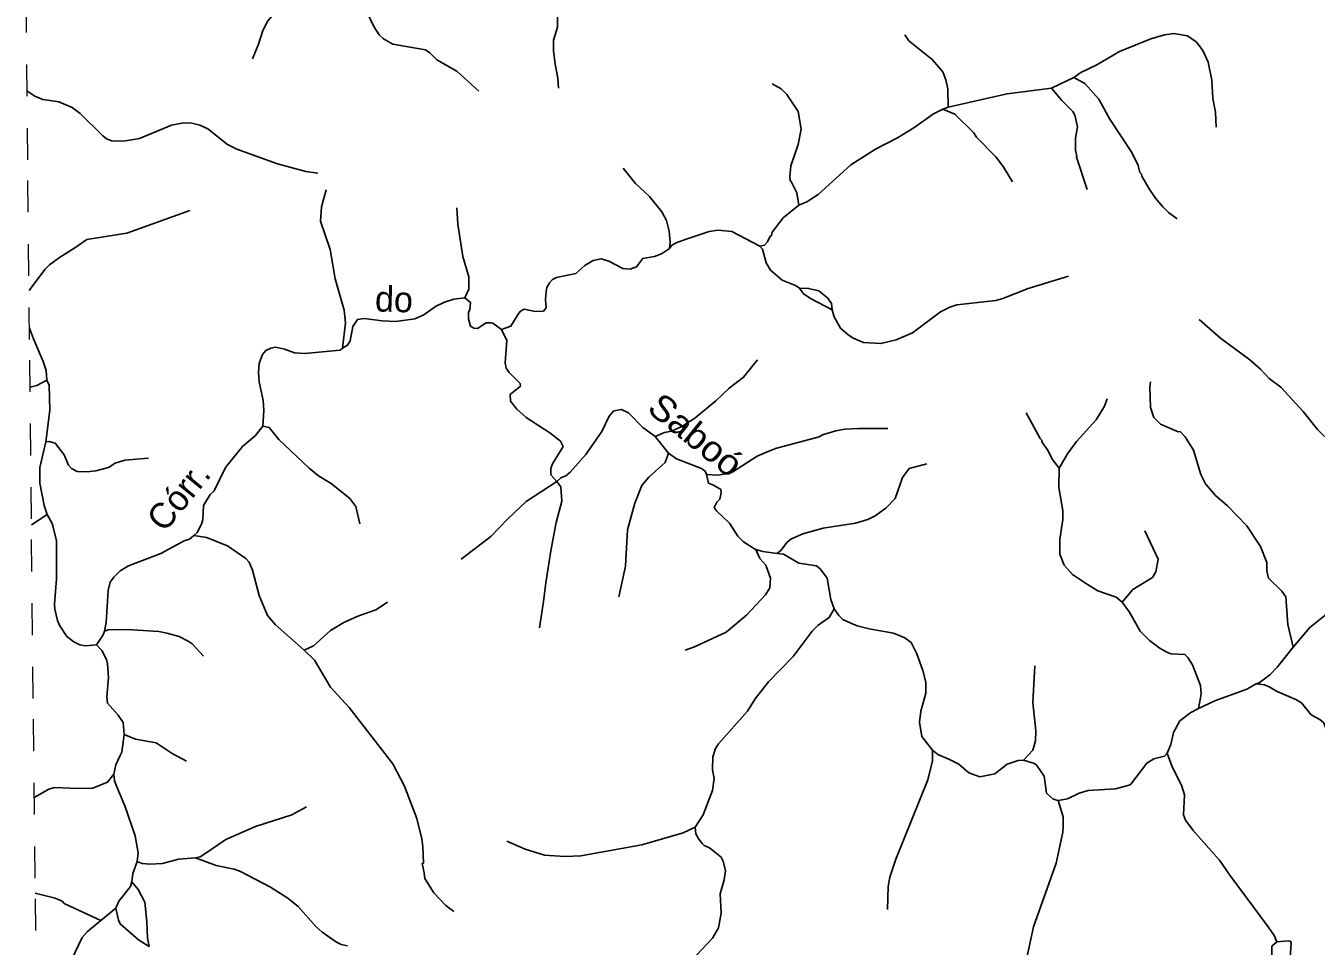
# Model space of a CAD drawing. Extents: x 346.5 to 372.4, y 7400.3 to 7428.2.
# Drawn here: x 346.625 to 350.684, y 7417.62 to 7420.515 of the extents above; entities that cross this region are included whole.
import ezdxf
from ezdxf.enums import TextEntityAlignment as Align

# ---------------------------------------------------------------- set-up
doc = ezdxf.new("R2010")
doc.units = 0
doc.header["$LTSCALE"] = 0.032
doc.linetypes.add('SHORT_DASHED', pattern=[2.7, 1.5, -1.2])
for name, color, linetype, lineweight in [('2', 7, 'Continuous', 25), ('53', 7, 'SHORT_DASHED', 13), ('7', 7, 'Continuous', 25)]:
    doc.layers.add(name, color=color, linetype=linetype, lineweight=lineweight)
doc.layers.add('61', color=7, linetype='Continuous')

msp = doc.modelspace()

# ---------------------------------------------------------------- linework, layer by layer
at = {"layer": '2'}
for points in [[(349.0587, 7419.6897), (349.0876, 7419.689), (349.1197, 7419.681), (349.1486, 7419.6579), (349.1598, 7419.6417), (349.1615, 7419.6212), (349.0936, 7419.6576), (349.071, 7419.6725)], [(346.9092, 7417.7395), (346.9181, 7417.7609), (346.9546, 7417.8075), (346.9588, 7417.8226), (346.9792, 7417.7976), (347.0001, 7417.758), (347.0065, 7417.6967), (347.0078, 7417.645), (347.0131, 7417.6189), (346.9804, 7417.6401), (346.9224, 7417.69), (346.9169, 7417.7019)], [(350.5445, 7417.5746), (350.5445, 7417.6194), (350.5603, 7417.6339), (350.5969, 7417.6371), (350.6034, 7417.6351), (350.6057, 7417.6305), (350.6019, 7417.5687), (350.6142, 7417.5248), (350.6164, 7417.4995), (350.6076, 7417.4794), (350.5878, 7417.4716), (350.5648, 7417.4992), (350.5572, 7417.5453)]]:
    msp.add_lwpolyline(points, close=True, dxfattribs=at)
at = {"layer": '53'}
msp.add_lwpolyline([(346.7311, 7410.4893), (346.7252, 7411.0543), (346.7194, 7411.6193), (346.7135, 7412.1842), (346.7076, 7412.7492), (346.7018, 7413.3141), (346.6959, 7413.8791), (346.69, 7414.444), (346.6841, 7415.009), (346.6783, 7415.574), (346.6724, 7416.1389), (346.6665, 7416.7039), (346.6607, 7417.2688), (346.6548, 7417.8338), (346.649, 7418.3987), (346.6431, 7418.9637), (346.6372, 7419.5286), (346.6314, 7420.0936), (346.6255, 7420.6585)], dxfattribs=at)
at = {"layer": '7'}
for p, q in [((346.6922, 7418.9778), (346.6433, 7418.9453)), ((346.9092, 7417.7395), (346.8612, 7417.7011))]:
    msp.add_line(p, q, dxfattribs=at)
for points in [[(348.1783, 7421.1943), (348.1763, 7421.1774), (348.1508, 7421.0993), (348.1413, 7421.0547), (348.1341, 7420.9622), (348.1349, 7420.9335), (348.1436, 7420.9048), (348.1532, 7420.8857), (348.217, 7420.7885), (348.2361, 7420.7534), (348.2839, 7420.6307), (348.2935, 7420.5972), (348.2983, 7420.5398), (348.2975, 7420.5111), (348.2855, 7420.4697), (348.2855, 7420.4378), (348.2903, 7420.3948), (348.299, 7420.3502), (348.3015, 7420.3191)], [(347.5673, 7420.8051), (347.518, 7420.7311), (347.4981, 7420.6849), (347.4806, 7420.6315), (347.4487, 7420.5908), (347.4073, 7420.555), (347.3873, 7420.5311), (347.3714, 7420.5), (347.3578, 7420.457), (347.3387, 7420.4115)], [(347.5673, 7420.8051), (347.5834, 7420.7685), (347.6232, 7420.7399), (347.6479, 7420.704), (347.6902, 7420.5765), (347.7205, 7420.5127), (347.7372, 7420.4872), (347.7507, 7420.4737), (347.7802, 7420.4569), (347.8823, 7420.4394), (347.8966, 7420.4298), (347.9181, 7420.4083), (347.9811, 7420.3725), (348.0504, 7420.3095)], [(349.3909, 7420.4864), (349.4036, 7420.4681), (349.4769, 7420.4091), (349.5096, 7420.3701), (349.5192, 7420.3454), (349.5255, 7420.3167), (349.5273, 7420.2596)], [(350.3703, 7420.1963), (350.3679, 7420.2434), (350.3592, 7420.2864), (350.356, 7420.3438), (350.3448, 7420.4012), (350.3289, 7420.4354), (350.3193, 7420.449), (350.3066, 7420.4649), (350.2795, 7420.484), (350.2364, 7420.4904), (350.2077, 7420.4872), (350.1647, 7420.4745), (350.0659, 7420.4338), (349.995, 7420.3924), (349.9439, 7420.3677), (349.9226, 7420.3521), (349.8517, 7420.319)], [(349.9226, 7420.3521), (349.9567, 7420.3334), (350.0005, 7420.284), (350.0356, 7420.2211), (350.1041, 7420.1167), (350.1249, 7420.0752), (350.1296, 7420.0537), (350.1352, 7420.0489), (350.136, 7420.0425), (350.1591, 7420.0019), (350.179, 7419.9724), (350.2022, 7419.9453), (350.2197, 7419.9278), (350.2468, 7419.9079)], [(347.5436, 7420.0513), (347.5061, 7420.0569), (347.4168, 7420.0808), (347.2893, 7420.127), (347.2598, 7420.1421), (347.1985, 7420.1908), (347.173, 7420.2027), (347.1475, 7420.2091), (347.122, 7420.2099), (347.0837, 7420.2027), (346.9833, 7420.1605), (346.9323, 7420.1517), (346.8956, 7420.1533), (346.8797, 7420.1597), (346.8677, 7420.1692), (346.7968, 7420.2394), (346.7713, 7420.2585), (346.7291, 7420.276), (346.6789, 7420.2832), (346.6534, 7420.2936), (346.6292, 7420.3103)], [(348.9733, 7420.3326), (349.0012, 7420.3167), (349.0195, 7420.2992), (349.0546, 7420.2458), (349.0641, 7420.19), (349.0546, 7420.1414), (349.0322, 7420.0744), (349.0283, 7420.0409), (349.0298, 7420.0274), (349.033, 7420.0258), (349.0506, 7419.9899), (349.057, 7419.9512)], [(349.8517, 7420.319), (349.712, 7420.3007), (349.5273, 7420.2596), (349.5104, 7420.2529)], [(349.8517, 7420.319), (349.8842, 7420.28), (349.9192, 7420.2458), (349.9256, 7420.2338), (349.9336, 7420.1971), (349.9272, 7420.1621), (349.9272, 7420.1238), (349.932, 7420.1055), (349.9304, 7420.1015), (349.9639, 7420.0003)], [(349.5104, 7420.2529), (349.4809, 7420.2378), (349.4188, 7420.1939), (349.367, 7420.1629), (349.2984, 7420.127), (349.2211, 7420.0776), (349.1175, 7419.9843), (349.0825, 7419.9612), (349.057, 7419.9512)], [(349.5104, 7420.2529), (349.5479, 7420.237), (349.6068, 7420.1796), (349.6164, 7420.1653), (349.677, 7420.1031), (349.7001, 7420.072), (349.7288, 7420.0242)], [(348.5047, 7420.0672), (348.5437, 7420.0186), (348.5875, 7419.978), (348.6266, 7419.9294), (348.6409, 7419.9023), (348.6489, 7419.8688), (348.6523, 7419.8345), (348.6501, 7419.8149)], [(347.5699, 7419.9987), (347.5555, 7419.9453), (347.5523, 7419.9007), (347.5834, 7419.8114), (347.5985, 7419.719), (347.6272, 7419.6202), (347.6312, 7419.5803), (347.6213, 7419.5012)], [(346.6356, 7419.6827), (346.6852, 7419.7485), (346.6996, 7419.7628), (346.7315, 7419.7859), (346.7801, 7419.817), (346.8175, 7419.8425), (346.9435, 7419.8632), (347.1419, 7419.9342)], [(347.9811, 7419.9429), (347.9843, 7419.8911), (348.0002, 7419.7891), (348.0193, 7419.7254), (348.0193, 7419.6871), (348.0068, 7419.6595)], [(349.057, 7419.9512), (349.0075, 7419.911), (348.9733, 7419.8664), (348.9709, 7419.8552), (348.9669, 7419.8529), (348.9585, 7419.8356), (348.9489, 7419.8253), (348.9348, 7419.8219)], [(348.9348, 7419.8219), (348.8466, 7419.868), (348.8035, 7419.872), (348.7748, 7419.868), (348.7031, 7419.8441), (348.6715, 7419.8321), (348.657, 7419.8239), (348.6501, 7419.8149)], [(348.6501, 7419.8149), (348.625, 7419.7979), (348.6027, 7419.7899), (348.566, 7419.7827), (348.5469, 7419.7572), (348.5262, 7419.7492), (348.5039, 7419.7516), (348.4592, 7419.7747), (348.4353, 7419.7819), (348.4098, 7419.7771), (348.3843, 7419.7612), (348.3556, 7419.7357), (348.2951, 7419.723), (348.2823, 7419.7174), (348.2727, 7419.707), (348.2648, 7419.6919), (348.2624, 7419.6791), (348.26, 7419.6536), (348.2624, 7419.6281), (348.2536, 7419.6178), (348.2281, 7419.6162), (348.1931, 7419.6233), (348.1819, 7419.6177), (348.1739, 7419.6082), (348.1516, 7419.5699), (348.1221, 7419.5598)], [(348.9348, 7419.8219), (348.943, 7419.8122), (348.9541, 7419.7692), (348.9677, 7419.7469), (349.0051, 7419.715), (349.0463, 7419.6985), (349.0587, 7419.6897)], [(349.9057, 7419.727), (349.779, 7419.6887), (349.6993, 7419.6568), (349.677, 7419.6512), (349.5543, 7419.6369), (349.5319, 7419.6305), (349.5024, 7419.6154), (349.4148, 7419.5492), (349.363, 7419.5277), (349.3152, 7419.5157), (349.261, 7419.5189), (349.2283, 7419.5325), (349.2108, 7419.5436), (349.1884, 7419.5636), (349.1685, 7419.5994), (349.1615, 7419.6212)], [(348.0068, 7419.6595), (347.9715, 7419.6552), (347.9428, 7419.6456), (347.9141, 7419.6321), (347.8775, 7419.6058), (347.8488, 7419.593), (347.7898, 7419.5851), (347.7468, 7419.5867), (347.6894, 7419.5946), (347.6687, 7419.5915), (347.6543, 7419.5692), (347.6463, 7419.5237), (347.6371, 7419.5109), (347.6213, 7419.5012)], [(348.0068, 7419.6595), (348.0241, 7419.6449), (348.0225, 7419.6225), (348.0177, 7419.613), (348.0177, 7419.5931), (348.0241, 7419.5707), (348.0345, 7419.5636), (348.0464, 7419.5628), (348.0735, 7419.5811), (348.0895, 7419.5803), (348.095, 7419.5795), (348.1221, 7419.5598)], [(350.3169, 7419.5907), (350.3831, 7419.5325), (350.4755, 7419.4647), (350.5098, 7419.4353), (350.5369, 7419.4058), (350.5735, 7419.3779), (350.6437, 7419.3022), (350.6883, 7419.2448), (350.7313, 7419.2033), (350.764, 7419.1786), (350.7975, 7419.1595), (350.8612, 7419.142), (350.8772, 7419.1332), (350.8962, 7419.1144)], [(346.692, 7419.4007), (346.6892, 7419.4305), (346.6804, 7419.4592), (346.6494, 7419.5309), (346.6368, 7419.5644)], [(348.1221, 7419.5598), (348.1389, 7419.5253), (348.1333, 7419.4544), (348.1365, 7419.4385), (348.146, 7419.4249), (348.1803, 7419.3898), (348.1819, 7419.3819), (348.1492, 7419.3555), (348.15, 7419.3341), (348.1699, 7419.3094), (348.1994, 7419.283), (348.2736, 7419.2352), (348.3078, 7419.2081), (348.3158, 7419.1914), (348.2823, 7419.1372), (348.2775, 7419.1229), (348.2775, 7419.1021), (348.2964, 7419.0811)], [(347.6213, 7419.5012), (347.6144, 7419.4944), (347.5029, 7419.4847), (347.471, 7419.4863), (347.4392, 7419.4982), (347.4105, 7419.5038), (347.3961, 7419.5014), (347.3802, 7419.4942), (347.3698, 7419.4815), (347.3594, 7419.4528), (347.3571, 7419.4241), (347.3594, 7419.3954), (347.3722, 7419.3364), (347.3738, 7419.3046), (347.3712, 7419.2552)], [(348.9271, 7419.4648), (348.8832, 7419.4097), (348.8378, 7419.3755), (348.7963, 7419.3356), (348.7302, 7419.2806), (348.6892, 7419.2542), (348.6569, 7419.2397), (348.6349, 7419.2356), (348.605, 7419.2235)], [(346.692, 7419.4007), (346.6605, 7419.3835), (346.6388, 7419.3787)], [(346.6889, 7419.2064), (346.7012, 7419.3062), (346.6989, 7419.3848), (346.692, 7419.4007)], [(350.1631, 7419.3946), (350.1607, 7419.3779), (350.1631, 7419.3141), (350.1743, 7419.283), (350.195, 7419.2615), (350.25, 7419.2376), (350.2564, 7419.2384), (350.2723, 7419.2217), (350.2986, 7419.1802), (350.3217, 7419.1037), (350.3368, 7419.0742), (350.3679, 7419.0376), (350.4054, 7419.0049), (350.4667, 7418.942), (350.5098, 7418.8774), (350.5297, 7418.8264), (350.5297, 7418.8009), (350.5345, 7418.7778), (350.5767, 7418.7363), (350.5887, 7418.7188), (350.595, 7418.6319), (350.6125, 7418.5604)], [(350.0268, 7419.342), (350.0189, 7419.3189), (349.9926, 7419.2751), (349.9304, 7419.2073), (349.9017, 7419.1691), (349.8764, 7419.1239)], [(348.2964, 7419.0811), (348.3086, 7419.093), (348.3238, 7419.0997), (348.3381, 7419.1109), (348.3867, 7419.1667), (348.4377, 7419.2392), (348.4608, 7419.287), (348.4752, 7419.3038), (348.4991, 7419.3077), (348.5214, 7419.2974), (348.5668, 7419.2512), (348.605, 7419.2235), (348.6472, 7419.1708)], [(349.7718, 7419.2974), (349.8164, 7419.2169), (349.822, 7419.2113), (349.822, 7419.2065), (349.8419, 7419.1779), (349.8539, 7419.1516), (349.8764, 7419.1239)], [(347.3712, 7419.2552), (347.3467, 7419.2249), (347.3068, 7419.1914), (347.2535, 7419.126), (347.2184, 7419.0519), (347.2056, 7419.0408), (347.1841, 7419.0057), (347.1825, 7418.9619), (347.1785, 7418.9475), (347.165, 7418.921), (347.154, 7418.9114)], [(347.3712, 7419.2552), (347.3905, 7419.2512), (347.4216, 7419.2137), (347.5164, 7419.1237), (347.5459, 7419.099), (347.5858, 7419.0758), (347.6448, 7419.028), (347.6639, 7419.0025), (347.6766, 7418.9483)], [(349.3367, 7419.2488), (349.245, 7419.2488), (349.202, 7419.2464), (349.1733, 7419.2408), (349.1318, 7419.2289), (349.1207, 7419.2217), (348.9836, 7419.185), (348.9549, 7419.1739), (348.9263, 7419.1611), (348.8498, 7419.1125), (348.8338, 7419.1069), (348.8019, 7419.1013), (348.767, 7419.1039)], [(346.6922, 7418.9778), (346.6828, 7419.0065), (346.6693, 7419.0766), (346.6693, 7419.1261), (346.6889, 7419.2064)], [(347.0112, 7419.1547), (346.9371, 7419.1491), (346.9068, 7419.1388), (346.8861, 7419.1252), (346.8462, 7419.1149), (346.8175, 7419.1117), (346.7873, 7419.1133), (346.7689, 7419.1221), (346.7601, 7419.1332), (346.7458, 7419.1659), (346.7179, 7419.2017), (346.6976, 7419.2072), (346.6889, 7419.2064)], [(348.6472, 7419.1708), (348.6362, 7419.1412), (348.5852, 7419.095), (348.5628, 7419.0687), (348.5413, 7419.0129), (348.5182, 7418.93), (348.5118, 7418.8152), (348.4911, 7418.7188)], [(348.6472, 7419.1708), (348.6728, 7419.1531), (348.7509, 7419.122), (348.7622, 7419.1142), (348.767, 7419.1039)], [(348.9893, 7418.8556), (349.0017, 7418.8659), (349.0195, 7418.8902), (349.0315, 7418.8997), (349.0697, 7418.9172), (349.1335, 7418.9348), (349.2355, 7418.9507), (349.2737, 7418.9619), (349.2976, 7418.9738), (349.3303, 7418.9977), (349.3598, 7419.028), (349.3829, 7419.0942), (349.4044, 7419.1221), (349.4594, 7419.1372)], [(349.8764, 7419.1239), (349.8746, 7419.0623), (349.8874, 7418.9906), (349.8874, 7418.9619), (349.8786, 7418.8997), (349.8778, 7418.8535), (349.8921, 7418.8184), (349.9184, 7418.7889), (349.9647, 7418.7578), (349.9981, 7418.7379), (350.0555, 7418.7172), (350.0745, 7418.7024)], [(347.9954, 7418.8368), (348.0879, 7418.9085), (348.1405, 7418.9635), (348.1994, 7419.0185), (348.2964, 7419.0811)], [(348.2964, 7419.0811), (348.3081, 7419.0646), (348.3118, 7419.0193), (348.2943, 7418.9523), (348.2767, 7418.8631), (348.2616, 7418.7626), (348.2536, 7418.7037), (348.2409, 7418.6216)], [(348.767, 7419.1039), (348.7725, 7419.0763), (348.7892, 7419.0702), (348.8115, 7419.0567), (348.8131, 7419.0464), (348.8083, 7419.0264), (348.7987, 7419.0161), (348.7908, 7419.0001), (348.7979, 7418.9898), (348.8394, 7418.9507), (348.8657, 7418.9093), (348.8832, 7418.8917), (348.9173, 7418.8701), (348.9214, 7418.8673)], [(346.8483, 7418.5682), (346.8128, 7418.565), (346.7952, 7418.5682), (346.7769, 7418.5769), (346.7546, 7418.5945), (346.733, 7418.6272), (346.7251, 7418.6447), (346.7163, 7418.6798), (346.7155, 7418.6957), (346.7219, 7418.7754), (346.7219, 7418.8949), (346.7107, 7418.942), (346.7084, 7418.9494), (346.6922, 7418.9778)], [(350.1456, 7418.926), (350.1878, 7418.8368), (350.1806, 7418.7969), (350.1695, 7418.7794), (350.1081, 7418.7419), (350.0745, 7418.7024)], [(350.897, 7418.9228), (350.8692, 7418.8949), (350.8469, 7418.8614), (350.8102, 7418.8312), (350.7911, 7418.8089), (350.7672, 7418.7642), (350.7544, 7418.7085), (350.7457, 7418.6957), (350.717, 7418.6638), (350.6644, 7418.6224), (350.6125, 7418.5604)], [(347.154, 7418.9114), (347.1403, 7418.9004), (347.1236, 7418.8949), (347.0502, 7418.8551), (346.9482, 7418.8168), (346.9219, 7418.8001), (346.9028, 7418.781), (346.8908, 7418.765), (346.8845, 7418.7387), (346.8781, 7418.6383), (346.8729, 7418.6105)], [(347.154, 7418.9114), (347.1937, 7418.9053), (347.2598, 7418.879), (347.318, 7418.8391), (347.3276, 7418.828), (347.3387, 7418.8025), (347.3594, 7418.7228), (347.3857, 7418.6598), (347.4112, 7418.6303), (347.5009, 7418.5511)], [(348.9214, 7418.8673), (348.9349, 7418.8396), (348.9533, 7418.8184), (348.9685, 7418.7778), (348.9661, 7418.7475), (348.9525, 7418.7252), (348.892, 7418.6614), (348.8282, 7418.608), (348.7286, 7418.561), (348.6991, 7418.5507)], [(348.9214, 7418.8673), (348.9435, 7418.8611), (348.9893, 7418.8556)], [(348.9893, 7418.8556), (349.0089, 7418.853), (349.057, 7418.8248), (349.1127, 7418.816), (349.1255, 7418.8057), (349.1462, 7418.7778), (349.1582, 7418.71), (349.1683, 7418.6807)], [(347.7635, 7418.7021), (347.7261, 7418.6782), (347.6703, 7418.6582), (347.6256, 7418.6383), (347.5842, 7418.6128), (347.5308, 7418.5642), (347.5009, 7418.5511)], [(349.1683, 7418.6807), (349.1526, 7418.6534), (349.1175, 7418.6295), (349.0992, 7418.6112), (349.0394, 7418.5307), (348.9621, 7418.451), (348.9199, 7418.3976), (348.8952, 7418.3594), (348.8043, 7418.2566), (348.7955, 7418.2414), (348.7868, 7418.2159), (348.786, 7418.1745), (348.7908, 7418.1474), (348.786, 7418.1092), (348.7557, 7418.0326), (348.7308, 7417.9941)], [(349.4773, 7418.2367), (349.4514, 7418.2701), (349.4443, 7418.2797), (349.4371, 7418.3243), (349.4411, 7418.3594), (349.457, 7418.416), (349.457, 7418.4502), (349.4474, 7418.4869), (349.4283, 7418.5395), (349.4108, 7418.5753), (349.3901, 7418.5897), (349.355, 7418.604), (349.2785, 7418.6184), (349.2403, 7418.6279), (349.2211, 7418.6359), (349.1956, 7418.6479), (349.1829, 7418.66), (349.1683, 7418.6807)], [(350.0745, 7418.7024), (350.0977, 7418.6702), (350.1304, 7418.6104), (350.1599, 7418.5817), (350.1942, 7418.5562), (350.2173, 7418.5435), (350.2285, 7418.5395), (350.2715, 7418.5371), (350.2803, 7418.5283), (350.2954, 7418.5044), (350.3209, 7418.4399), (350.3225, 7418.4136), (350.3201, 7418.4008), (350.3146, 7418.3678)], [(346.8729, 7418.6105), (346.8688, 7418.5994), (346.8483, 7418.5682)], [(346.8729, 7418.6105), (346.8848, 7418.615), (346.9451, 7418.616), (347.0439, 7418.6096), (347.0694, 7418.6048), (347.1076, 7418.5937), (347.1363, 7418.5793), (347.1491, 7418.5706), (347.1849, 7418.5323)], [(346.8483, 7418.5682), (346.8645, 7418.5499), (346.8797, 7418.522), (346.8829, 7418.5076), (346.8853, 7418.4646), (346.8805, 7418.404), (346.8821, 7418.3841), (346.9163, 7418.3466), (346.9315, 7418.3235), (346.9347, 7418.2855)], [(350.6125, 7418.5604), (350.5624, 7418.4981), (350.5385, 7418.4733), (350.5054, 7418.448), (350.4957, 7418.4446)], [(347.5009, 7418.5511), (347.5332, 7418.5196), (347.5842, 7418.4343), (347.6424, 7418.3705), (347.7802, 7418.1936), (347.8169, 7418.1235), (347.8551, 7418.0215), (347.8711, 7417.9577), (347.8743, 7417.9322), (347.8767, 7417.8812), (347.8727, 7417.8804), (347.8783, 7417.8509), (347.8807, 7417.8326), (347.9085, 7417.7872), (347.9468, 7417.7481), (347.9723, 7417.729)], [(349.7997, 7418.502), (349.7933, 7418.3865), (349.8021, 7418.2972), (349.8013, 7418.2654), (349.7933, 7418.2367), (349.7635, 7418.2045)], [(350.4957, 7418.4446), (350.466, 7418.4287), (350.3655, 7418.3913), (350.3146, 7418.3678)], [(350.4957, 7418.4446), (350.5214, 7418.4418), (350.5369, 7418.4359), (350.5616, 7418.4207), (350.6206, 7418.396), (350.6381, 7418.3849), (350.6692, 7418.3474), (350.6955, 7418.3331), (350.709, 7418.3219), (350.7305, 7418.259), (350.7409, 7418.239), (350.7544, 7418.2247), (350.7815, 7418.2119), (350.8326, 7418.2024), (350.8565, 7418.1888), (350.8676, 7418.1769), (350.8772, 7418.157), (350.8835, 7418.1235), (350.9027, 7418.0988), (350.9282, 7418.0884), (350.9779, 7418.0837)], [(350.3146, 7418.3678), (350.2906, 7418.3554), (350.2555, 7418.3283), (350.2356, 7418.2924), (350.2269, 7418.2542), (350.2158, 7418.2272)], [(346.9347, 7418.2855), (346.9275, 7418.2303), (346.9211, 7418.2175), (346.9084, 7418.1904), (346.9022, 7418.1609)], [(346.9347, 7418.2855), (346.9706, 7418.2709), (347.0359, 7418.2598), (347.0861, 7418.2255), (347.1307, 7418.2016)], [(349.4773, 7418.2367), (349.4777, 7418.2032), (349.4634, 7418.1426), (349.3622, 7417.894), (349.3438, 7417.8366), (349.3383, 7417.8079), (349.3359, 7417.7354)], [(349.7635, 7418.2045), (349.747, 7418.2038), (349.7128, 7418.1928), (349.6738, 7418.1617), (349.626, 7418.1522), (349.5917, 7418.1649), (349.5606, 7418.192), (349.5287, 7418.208), (349.4945, 7418.223), (349.4773, 7418.2367)], [(349.873, 7418.0782), (349.8571, 7418.0827), (349.8364, 7418.1012), (349.8284, 7418.1546), (349.8053, 7418.188), (349.7983, 7418.1946), (349.7635, 7418.2045)], [(350.2158, 7418.2272), (350.2069, 7418.2176), (350.1743, 7418.2087), (350.1519, 7418.1952), (350.1017, 7418.1291), (350.0962, 7418.1267), (350.0531, 7418.1147), (349.9671, 7418.1091), (349.9384, 7418.1012), (349.9017, 7418.0828), (349.873, 7418.0782)], [(350.2158, 7418.2272), (350.2316, 7418.1841), (350.2603, 7418.1267), (350.2699, 7418.0964), (350.2675, 7418.0326), (350.2731, 7418.0167), (350.2978, 7417.984), (350.3807, 7417.89), (350.4125, 7417.843), (350.5337, 7417.6804), (350.5526, 7417.6533), (350.5603, 7417.6339)], [(346.9022, 7418.1609), (346.8829, 7418.1362), (346.8367, 7418.1171), (346.7904, 7418.1155), (346.7155, 7418.1187), (346.698, 7418.1139), (346.6522, 7418.087)], [(346.9022, 7418.1609), (346.9049, 7418.1402), (346.9114, 7418.1214), (346.9371, 7418.0613), (346.9697, 7417.9673), (346.9785, 7417.9131), (346.9757, 7417.8867)], [(349.873, 7418.0782), (349.8889, 7418.0263), (349.8889, 7417.9976), (349.8874, 7417.9785), (349.8666, 7417.8812), (349.7949, 7417.6804), (349.7678, 7417.5545), (349.6905, 7417.2795)], [(347.5085, 7418.0581), (347.4623, 7418.0326), (347.3483, 7417.9968), (347.2551, 7417.9553), (347.1889, 7417.9099), (347.1735, 7417.9007), (347.1591, 7417.8973)], [(348.7308, 7417.9941), (348.6935, 7417.9768), (348.5629, 7417.9386), (348.3716, 7417.9043), (348.3206, 7417.9019), (348.2568, 7417.9059), (348.1963, 7417.925), (348.1381, 7417.9498)], [(348.7308, 7417.9941), (348.7335, 7417.9735), (348.7421, 7417.9561), (348.7533, 7417.9426), (348.7597, 7417.9362), (348.7756, 7417.929), (348.8131, 7417.8995), (348.8194, 7417.8876), (348.8266, 7417.8573), (348.8218, 7417.8286), (348.8099, 7417.784), (348.8131, 7417.7234), (348.8043, 7417.6772), (348.786, 7417.6453), (348.7366, 7417.5927), (348.723, 7417.564), (348.7143, 7417.5353), (348.7127, 7417.4748), (348.6911, 7417.4155)], [(346.9757, 7417.8867), (346.9626, 7417.8485), (346.9588, 7417.8226)], [(347.1591, 7417.8973), (347.106, 7417.894), (347.055, 7417.8804), (347.0168, 7417.878), (346.9913, 7417.8796), (346.9757, 7417.8867)], [(347.1591, 7417.8973), (347.224, 7417.874), (347.2814, 7417.8621), (347.3005, 7417.8549), (347.3953, 7417.8055), (347.4495, 7417.7704), (347.4822, 7417.7441), (347.538, 7417.682), (347.5579, 7417.6644), (347.6033, 7417.6326), (347.6177, 7417.6254), (347.6376, 7417.6206)], [(346.6553, 7417.7867), (346.7179, 7417.7712), (346.7394, 7417.7609), (346.7466, 7417.7537), (346.8612, 7417.7011)], [(346.8612, 7417.7011), (346.8199, 7417.666), (346.8032, 7417.6469), (346.7689, 7417.5768), (346.7482, 7417.5481), (346.7386, 7417.5425), (346.6977, 7417.5353)]]:
    msp.add_lwpolyline(points, dxfattribs=at)

# ---------------------------------------------------------------- texts
at = {"layer": '61'}
for s, rotation, p in [('do', 358.253, (347.7825, 7419.615)), ('Córr.', 50.759, (347.137, 7419.0106))]:
    msp.add_text(s, height=0.08, rotation=rotation, dxfattribs=at).set_placement(p, align=Align.CENTER)
at = {"layer": '61', "width": 1.1}
msp.add_text('Saboó', height=0.08, rotation=320.967, dxfattribs=at).set_placement((348.7078, 7419.1972), align=Align.CENTER)

doc.saveas('drawing.dxf')
